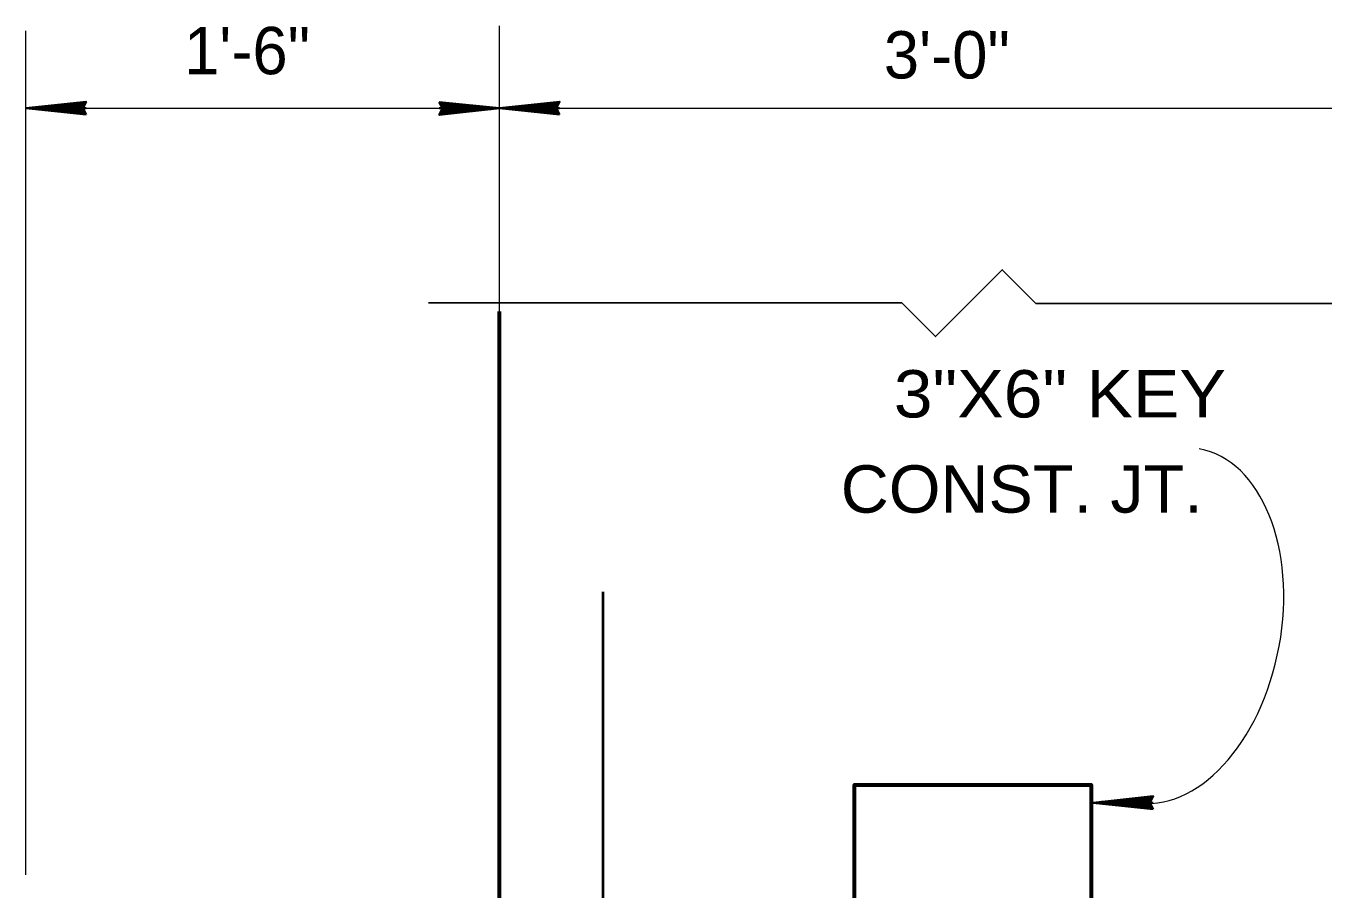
# Model space of a CAD drawing. Extents: x 14.14 to 17.34, y -1.61 to 0.38.
# Drawn here: x 15.5065 to 15.7348, y 0.0707 to 0.2226 of the extents above; entities that cross this region are included whole.
import ezdxf

# ---------------------------------------------------------------- set-up
doc = ezdxf.new("R2010")
doc.units = 0
doc.header["$LTSCALE"] = 0.0033
doc.layers.add('1', color=7, linetype='Continuous', lineweight=40)

msp = doc.modelspace()

# ---------------------------------------------------------------- linework, layer by layer
at = {"layer": '1', "lineweight": 13}
for p, q in [((15.5065, 0.073167), (15.5065, 0.22175)), ((15.589833, 0.172333), (15.589833, 0.222583)), ((15.507083, 0.208083), (15.837333, 0.208083))]:
    msp.add_line(p, q, dxfattribs=at)
at = {"layer": '1', "lineweight": 35}
for p, q in [((15.517083, 0.208083), (15.5065, 0.208083)), ((15.516833, 0.20725), (15.509, 0.20825)), ((15.516833, 0.20725), (15.509, 0.208083)), ((15.516833, 0.207083), (15.509, 0.208)), ((15.516833, 0.207083), (15.509, 0.208)), ((15.516833, 0.207167), (15.509, 0.208)), ((15.516833, 0.209167), (15.5095, 0.208333)), ((15.516833, 0.209), (15.5095, 0.20825)), ((15.516833, 0.208917), (15.5095, 0.208083)), ((15.516917, 0.20875), (15.509583, 0.208)), ((15.57925, 0.208083), (15.589833, 0.208083)), ((15.579417, 0.207417), (15.58675, 0.208167)), ((15.5795, 0.209083), (15.587333, 0.208167)), ((15.5795, 0.209083), (15.587333, 0.208167)), ((15.5795, 0.209), (15.587333, 0.208167)), ((15.5795, 0.208917), (15.587333, 0.208083)), ((15.5795, 0.208917), (15.587333, 0.207917)), ((15.5795, 0.20725), (15.586833, 0.208083)), ((15.5795, 0.207167), (15.586833, 0.207917)), ((15.5795, 0.207), (15.586833, 0.207833)), ((15.600417, 0.208083), (15.589833, 0.208083)), ((15.600167, 0.20725), (15.592333, 0.20825)), ((15.600167, 0.20725), (15.592333, 0.208083)), ((15.600167, 0.207083), (15.592333, 0.208)), ((15.600167, 0.207083), (15.592333, 0.208)), ((15.600167, 0.207167), (15.592333, 0.208)), ((15.600167, 0.209167), (15.592833, 0.208333)), ((15.600167, 0.209), (15.592833, 0.20825)), ((15.600167, 0.208917), (15.592833, 0.208083)), ((15.60025, 0.20875), (15.592917, 0.208)), ((15.704667, 0.086917), (15.697333, 0.086083)), ((15.704917, 0.085833), (15.694333, 0.085833)), ((15.704667, 0.085), (15.696833, 0.086)), ((15.704667, 0.085), (15.696833, 0.085833)), ((15.704667, 0.084833), (15.696833, 0.08575)), ((15.704667, 0.084833), (15.696833, 0.08575)), ((15.704667, 0.084917), (15.696833, 0.08575)), ((15.704667, 0.08675), (15.697333, 0.086)), ((15.704667, 0.086667), (15.697333, 0.085833)), ((15.70475, 0.0865), (15.697417, 0.08575))]:
    msp.add_line(p, q, dxfattribs=at)
for points in [[(15.517083, 0.207), (15.5065, 0.208083), (15.517083, 0.20925), (15.5165, 0.208083)], [(15.516333, 0.208), (15.511667, 0.207917), (15.511667, 0.208), (15.512583, 0.208), (15.516333, 0.207917), (15.513333, 0.207833), (15.5165, 0.20775), (15.51425, 0.207667), (15.5165, 0.207583), (15.513, 0.207833), (15.508333, 0.208), (15.50925, 0.20825), (15.508, 0.20825), (15.516333, 0.20825), (15.513917, 0.208417), (15.5165, 0.208417), (15.511167, 0.208), (15.5165, 0.208667)], [(15.57925, 0.209167), (15.589833, 0.208083), (15.57925, 0.206917), (15.579833, 0.208083)], [(15.58, 0.208167), (15.584667, 0.20825), (15.584667, 0.208167), (15.58375, 0.208167), (15.58, 0.20825), (15.583, 0.208333), (15.579833, 0.208417), (15.582083, 0.2085), (15.579833, 0.208583), (15.583333, 0.208333), (15.588, 0.208167), (15.587083, 0.207917), (15.588333, 0.207917), (15.58, 0.207917), (15.582417, 0.20775), (15.579833, 0.20775), (15.585167, 0.208167), (15.579833, 0.2075)], [(15.600417, 0.207), (15.589833, 0.208083), (15.600417, 0.20925), (15.599833, 0.208083)], [(15.599667, 0.208), (15.595, 0.207917), (15.595, 0.208), (15.595917, 0.208), (15.599667, 0.207917), (15.596667, 0.207833), (15.599833, 0.20775), (15.597583, 0.207667), (15.599833, 0.207583), (15.596333, 0.207833), (15.591667, 0.208), (15.592583, 0.20825), (15.591333, 0.20825), (15.599667, 0.20825), (15.59725, 0.208417), (15.599833, 0.208417), (15.5945, 0.208), (15.599833, 0.208667)], [(15.704917, 0.08475), (15.694333, 0.085833), (15.704917, 0.087), (15.704333, 0.085833)], [(15.704167, 0.08575), (15.6995, 0.085667), (15.6995, 0.08575), (15.700417, 0.08575), (15.704167, 0.085667), (15.701167, 0.085583), (15.704333, 0.0855), (15.702083, 0.085417), (15.704333, 0.085333), (15.700833, 0.085583), (15.696167, 0.08575), (15.697083, 0.086), (15.695833, 0.086), (15.704167, 0.086), (15.70175, 0.086167), (15.704333, 0.086167), (15.699, 0.08575), (15.704333, 0.086417)]]:
    msp.add_lwpolyline(points, close=True, dxfattribs=at)
for points in [[(15.516333, 0.208), (15.51675, 0.20725), (15.5165, 0.2075), (15.516333, 0.207833), (15.516083, 0.20775), (15.51625, 0.207417), (15.516417, 0.208167), (15.516583, 0.208667), (15.516833, 0.209083)], [(15.58, 0.208167), (15.579583, 0.208917), (15.579833, 0.208667), (15.58, 0.208333), (15.58025, 0.208417), (15.580083, 0.20875), (15.579917, 0.208), (15.57975, 0.2075), (15.5795, 0.207083)], [(15.599667, 0.208), (15.600083, 0.20725), (15.599833, 0.2075), (15.599667, 0.207833), (15.599417, 0.20775), (15.599583, 0.207417), (15.59975, 0.208167), (15.599917, 0.208667), (15.600167, 0.209083)], [(15.704167, 0.08575), (15.704583, 0.085), (15.704333, 0.08525), (15.704167, 0.085583), (15.703917, 0.0855), (15.704083, 0.085167), (15.70425, 0.085917), (15.704417, 0.086417), (15.704667, 0.086833)]]:
    msp.add_lwpolyline(points, dxfattribs=at)
at = {"layer": '1', "lineweight": 25}
msp.add_lwpolyline([(15.577333, 0.173833), (15.660667, 0.173833), (15.666583, 0.167917), (15.678333, 0.179667), (15.68425, 0.17375), (15.767583, 0.17375)], dxfattribs=at)
at = {"layer": '1', "lineweight": 60}
for points in [[(15.5065, 0.068167), (15.589833, 0.068167), (15.589833, 0.172333)], [(15.652333, 0.068167), (15.652333, 0.089), (15.694, 0.089), (15.694, 0.068167)]]:
    msp.add_lwpolyline(points, dxfattribs=at)
at = {"layer": '1'}
msp.add_lwpolyline([(15.545583, 0.010833), (15.608083, 0.010833), (15.608083, 0.123)], dxfattribs=at)
at = {"layer": '1', "lineweight": 13}
msp.add_ellipse((15.707292, 0.117042), major_axis=(0.005708, 0.031125), ratio=0.635583, start_param=3.1415927, end_param=6.2831853, dxfattribs=at)

# ---------------------------------------------------------------- texts
at = {"layer": '1'}
for s, p in [('1\'-6"', (15.534333, 0.214083)), ('3\'-0"', (15.6575, 0.213333))]:
    msp.add_text(s, height=0.008333, dxfattribs=at).set_placement(p)
for s, width, p in [('3"X6" KEY', 1.1, (15.65925, 0.153667)), ('CONST. JT. ', 1.05, (15.649917, 0.136917))]:
    msp.add_text(s, height=0.008334, dxfattribs=dict(at, width=width)).set_placement(p)

doc.saveas('drawing.dxf')
